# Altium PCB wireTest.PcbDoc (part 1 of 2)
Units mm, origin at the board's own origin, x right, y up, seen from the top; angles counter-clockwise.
Board outline 121.22 x 130.26 mm, 2 copper layers (Top Layer, Bottom Layer); 157 components, 144 nets, 513 pads, 186 vias.
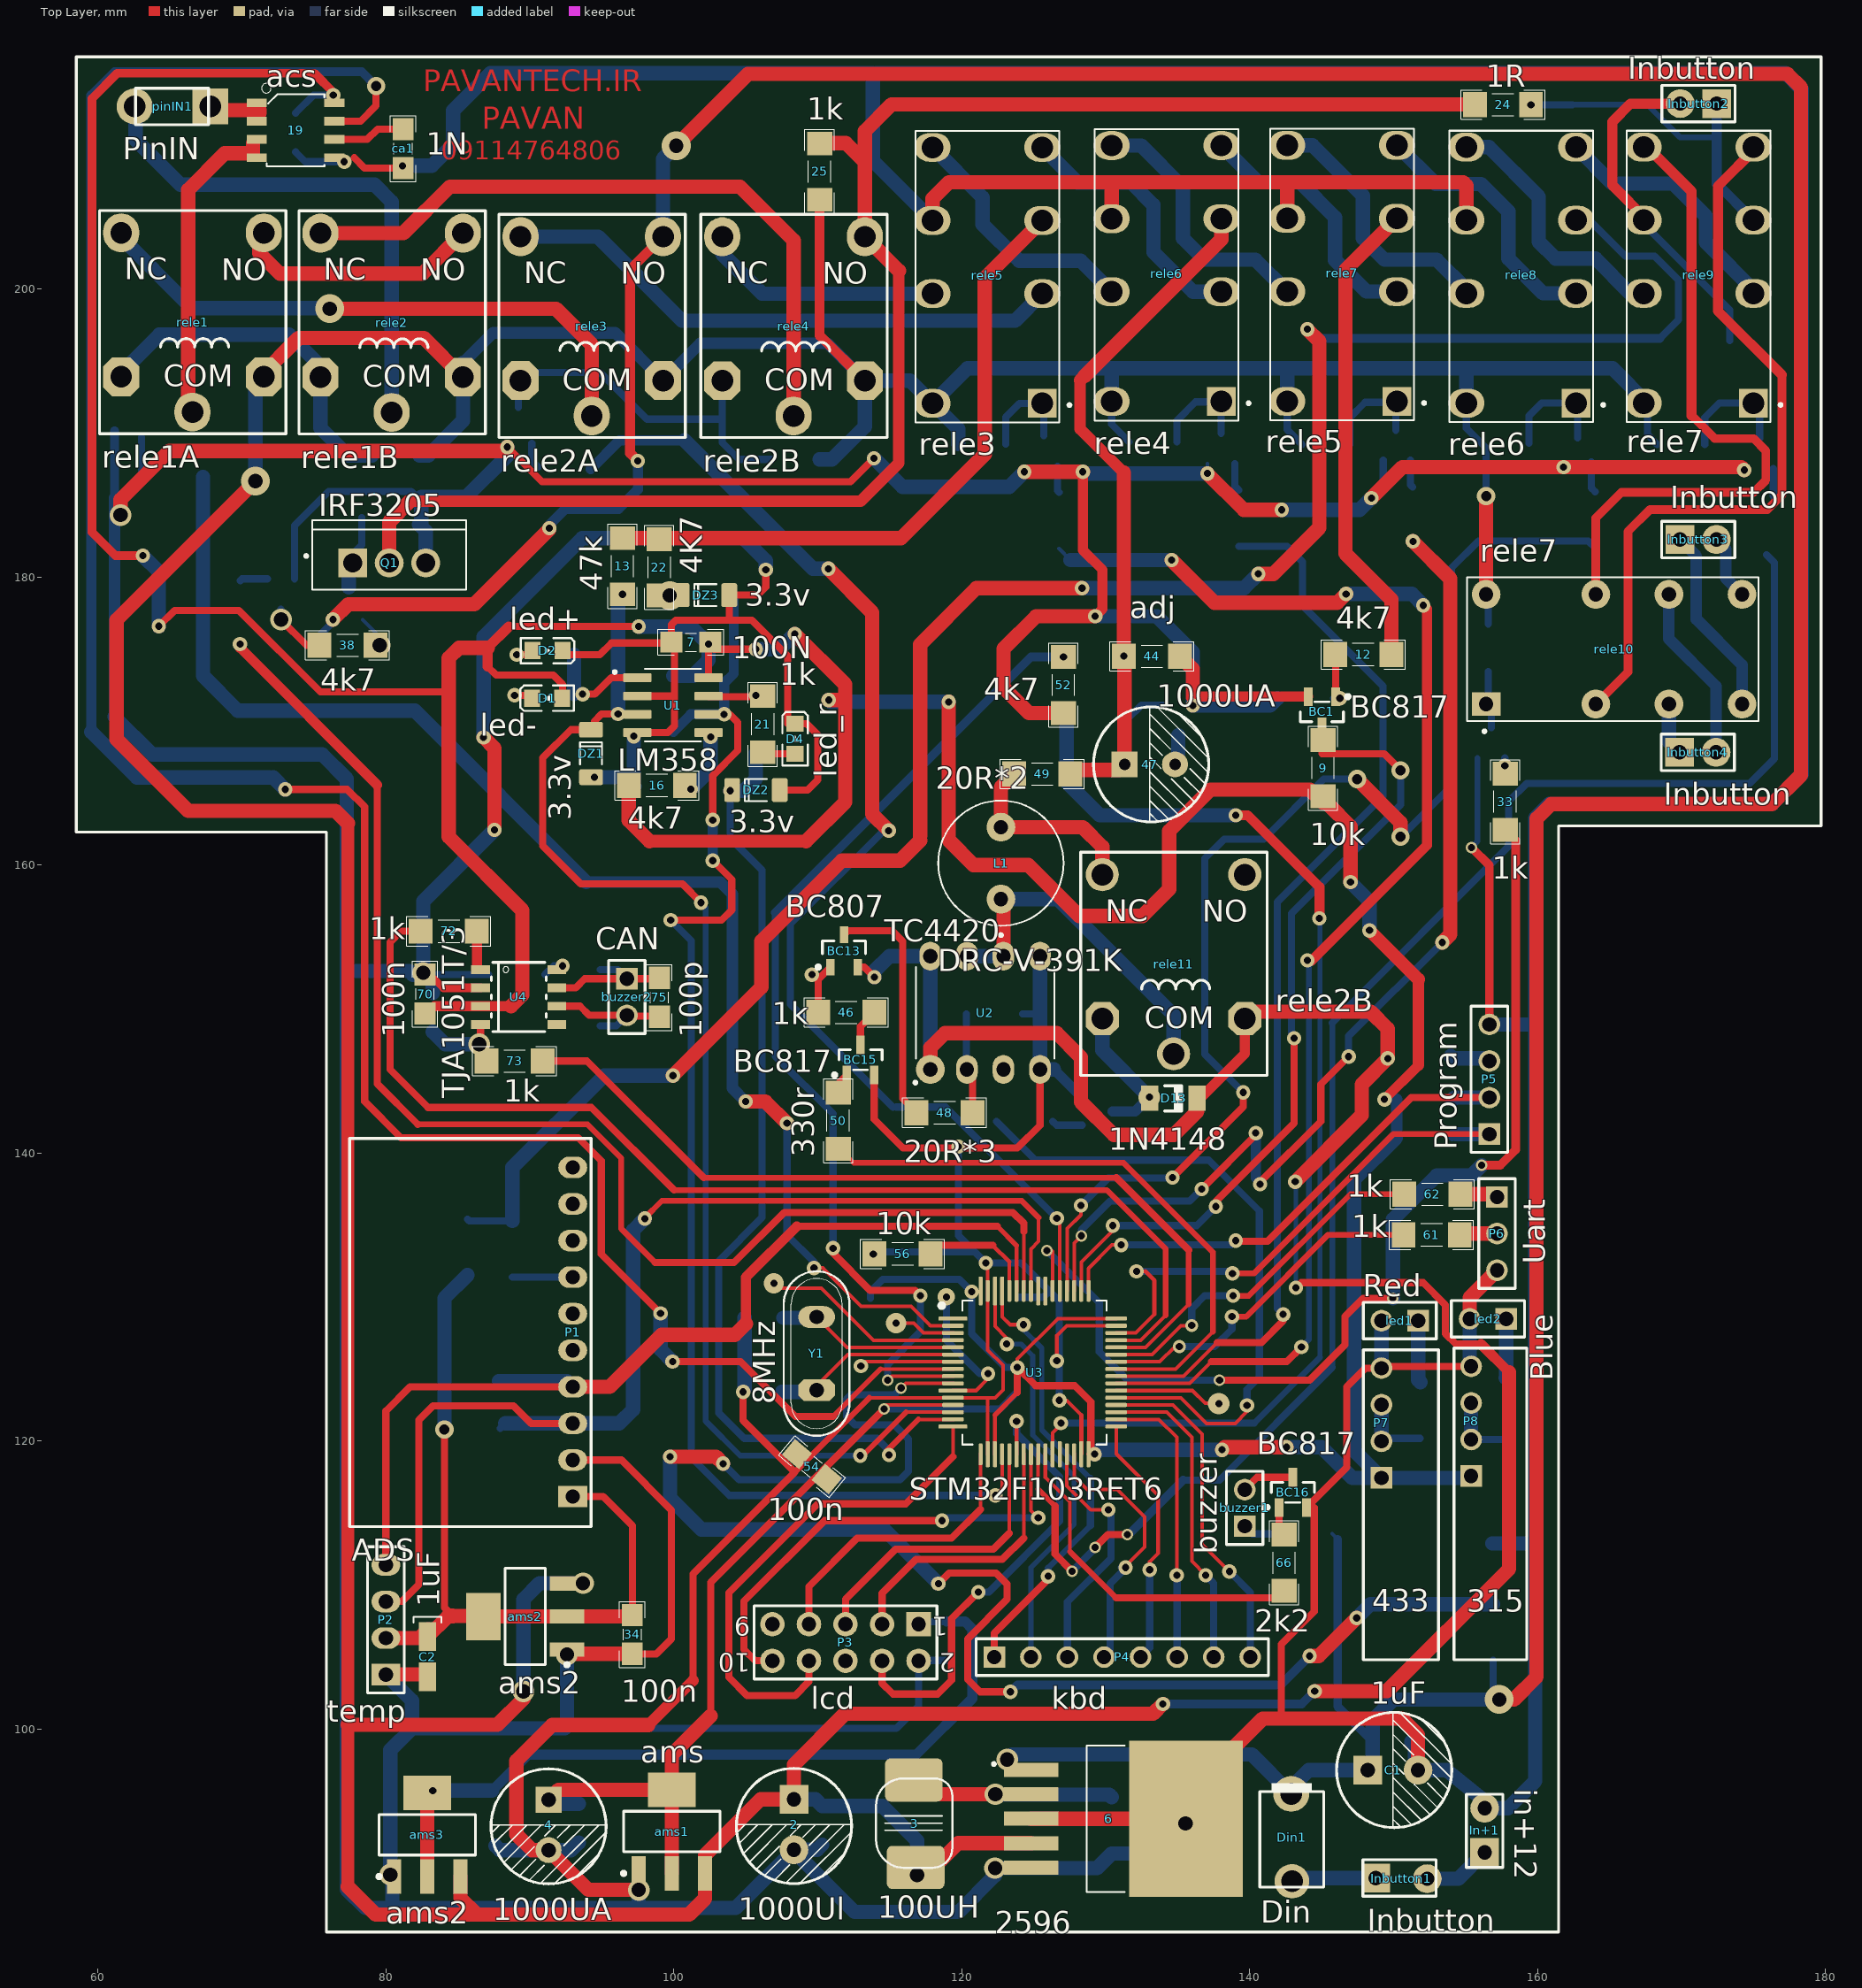
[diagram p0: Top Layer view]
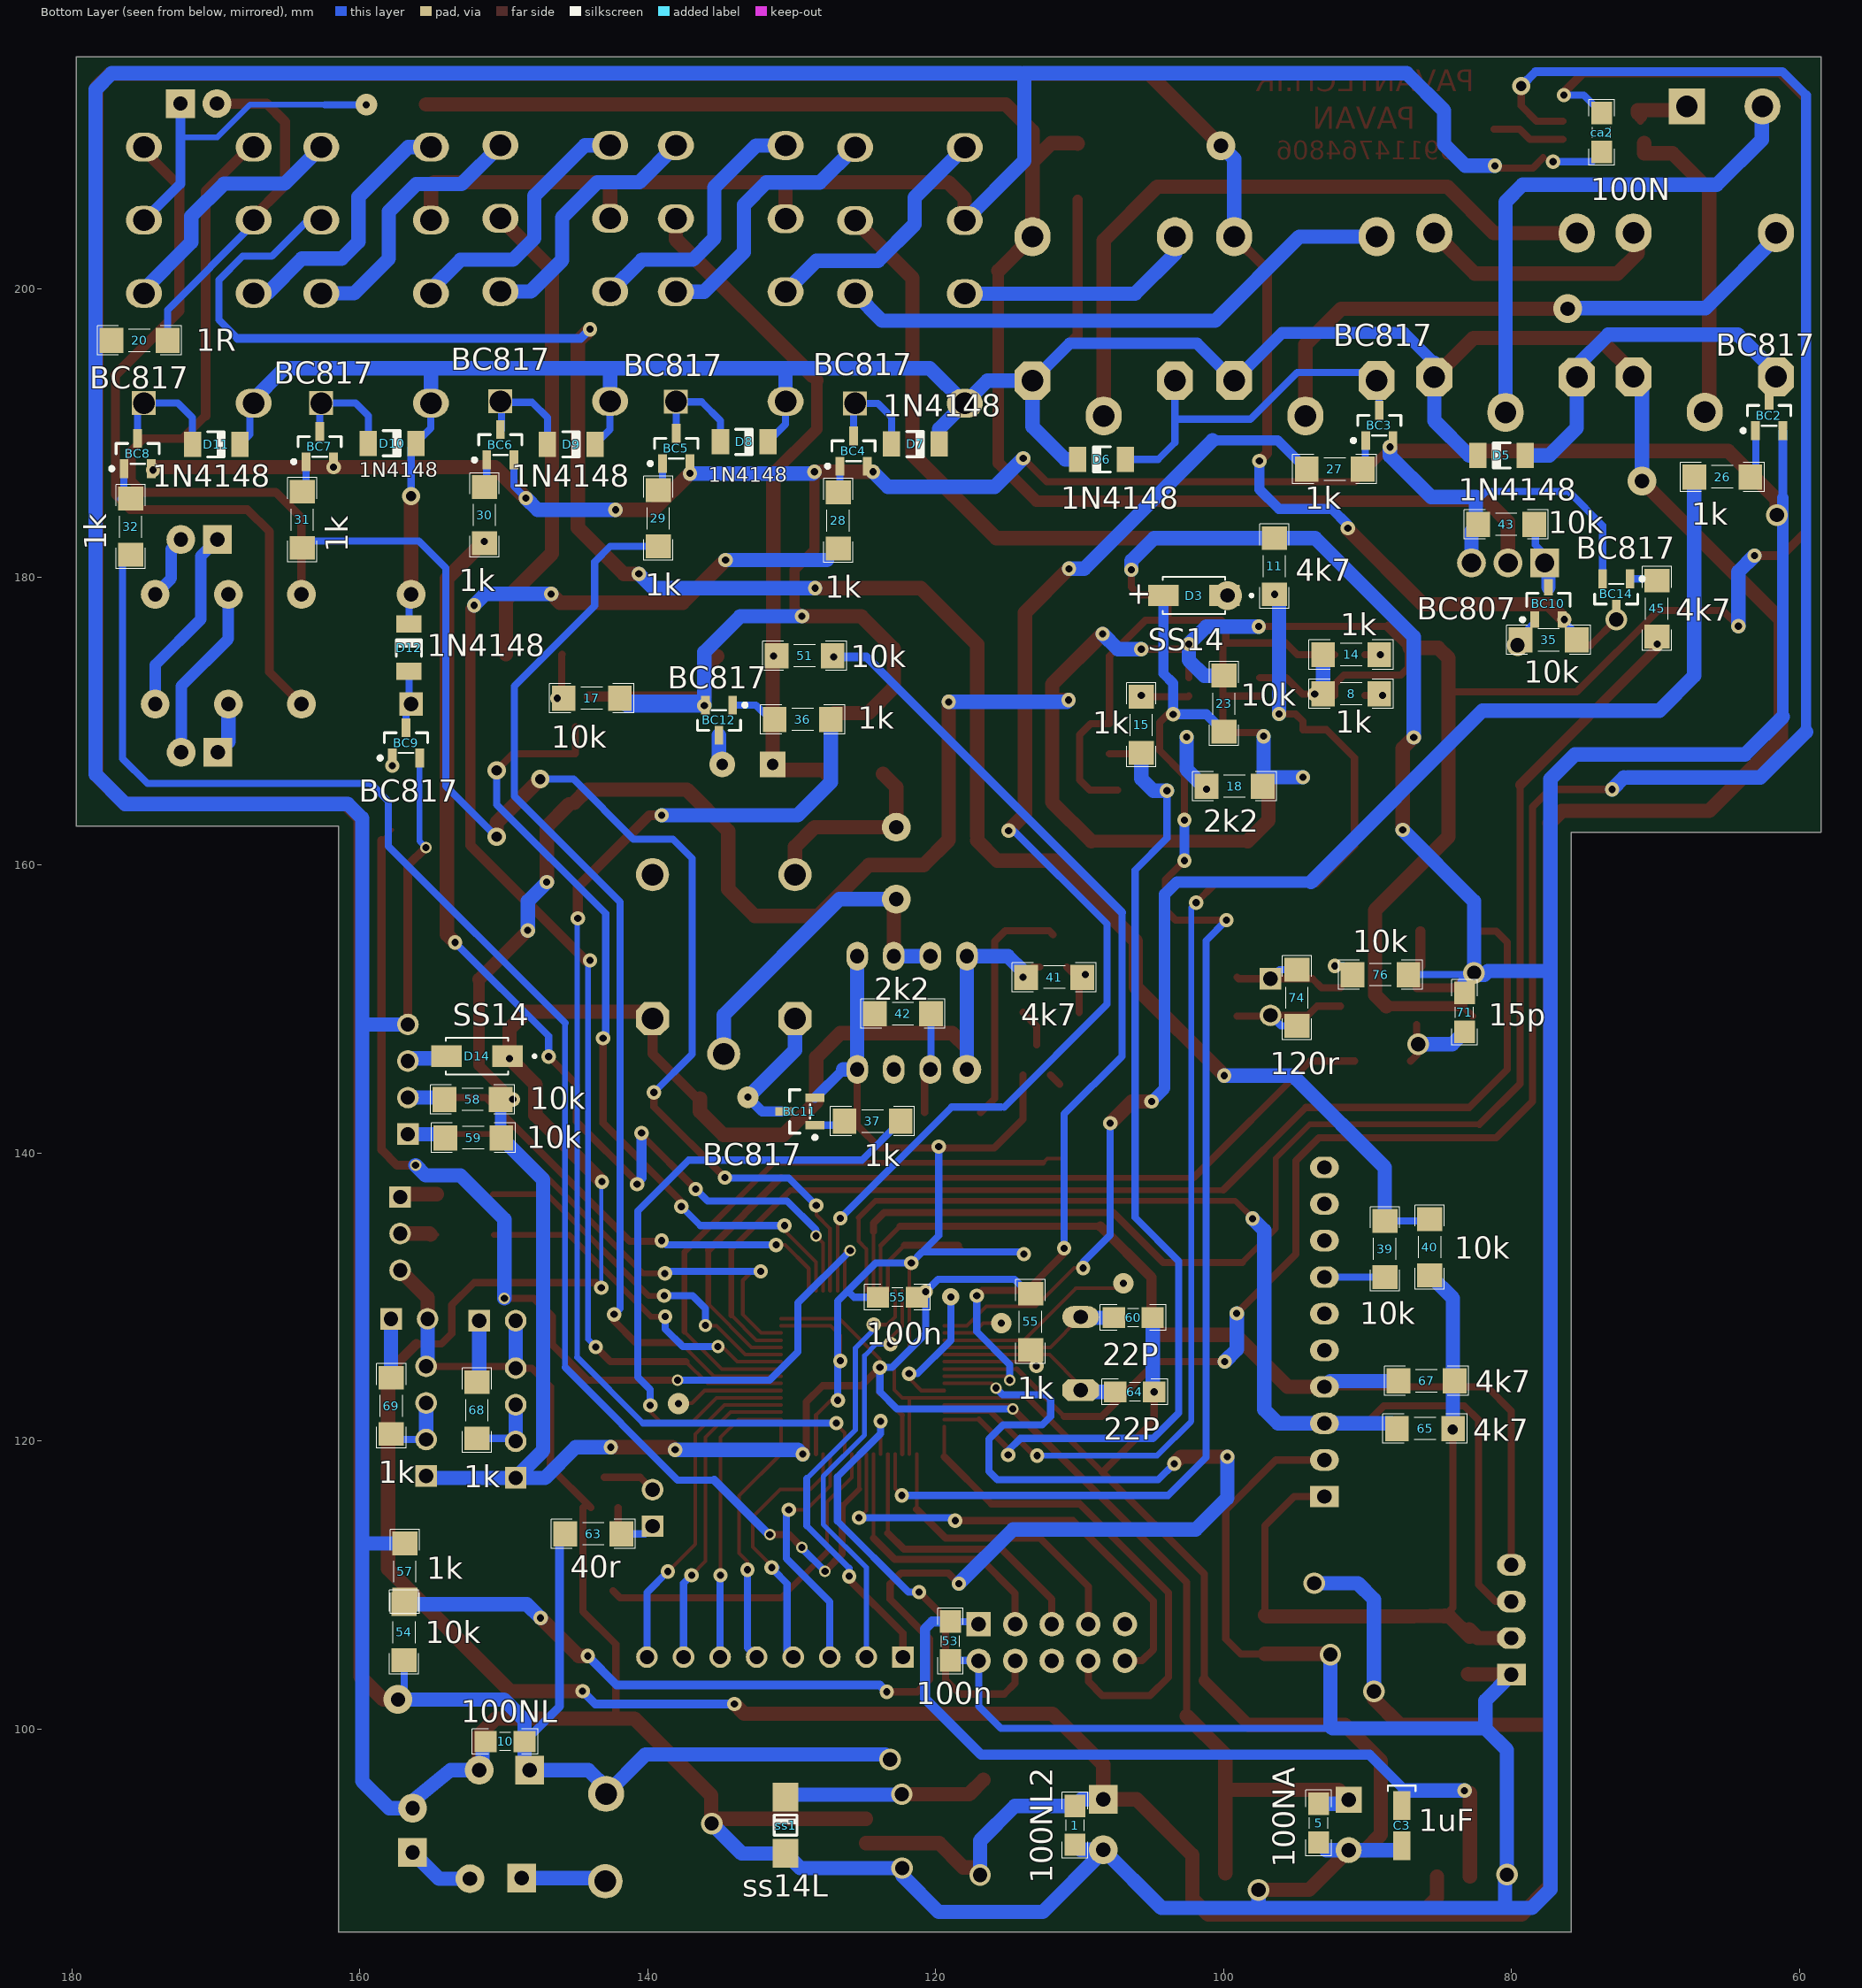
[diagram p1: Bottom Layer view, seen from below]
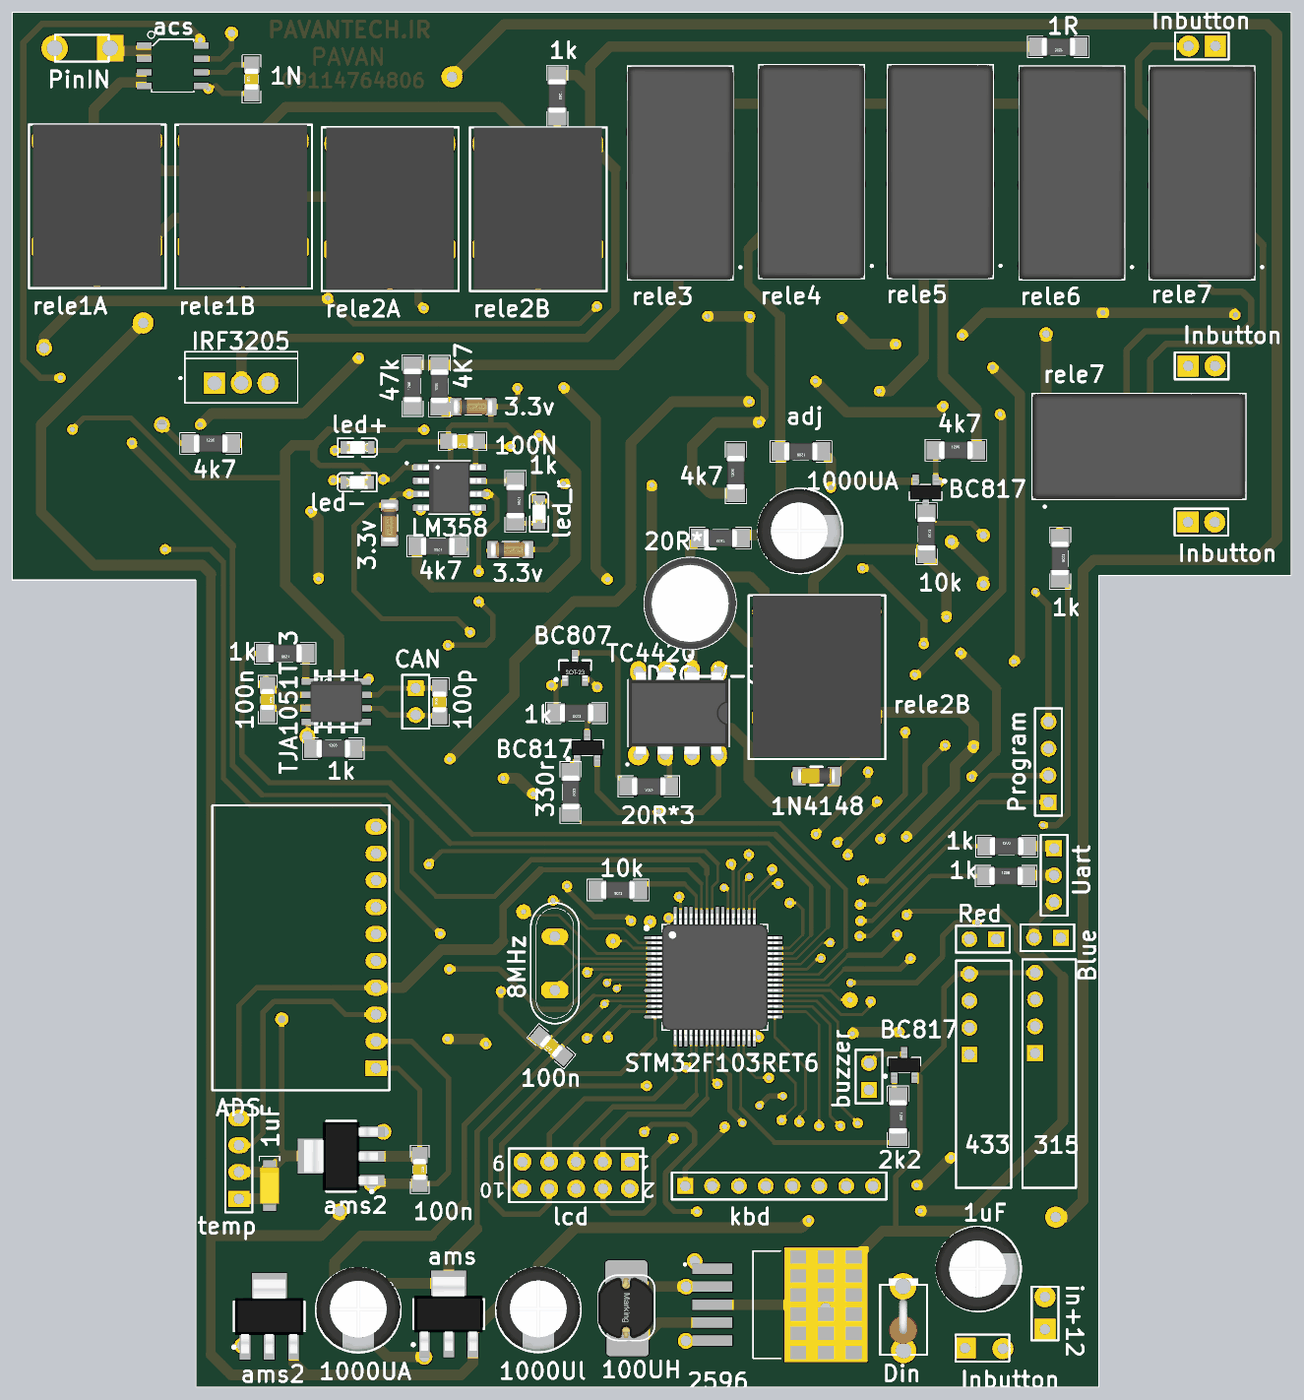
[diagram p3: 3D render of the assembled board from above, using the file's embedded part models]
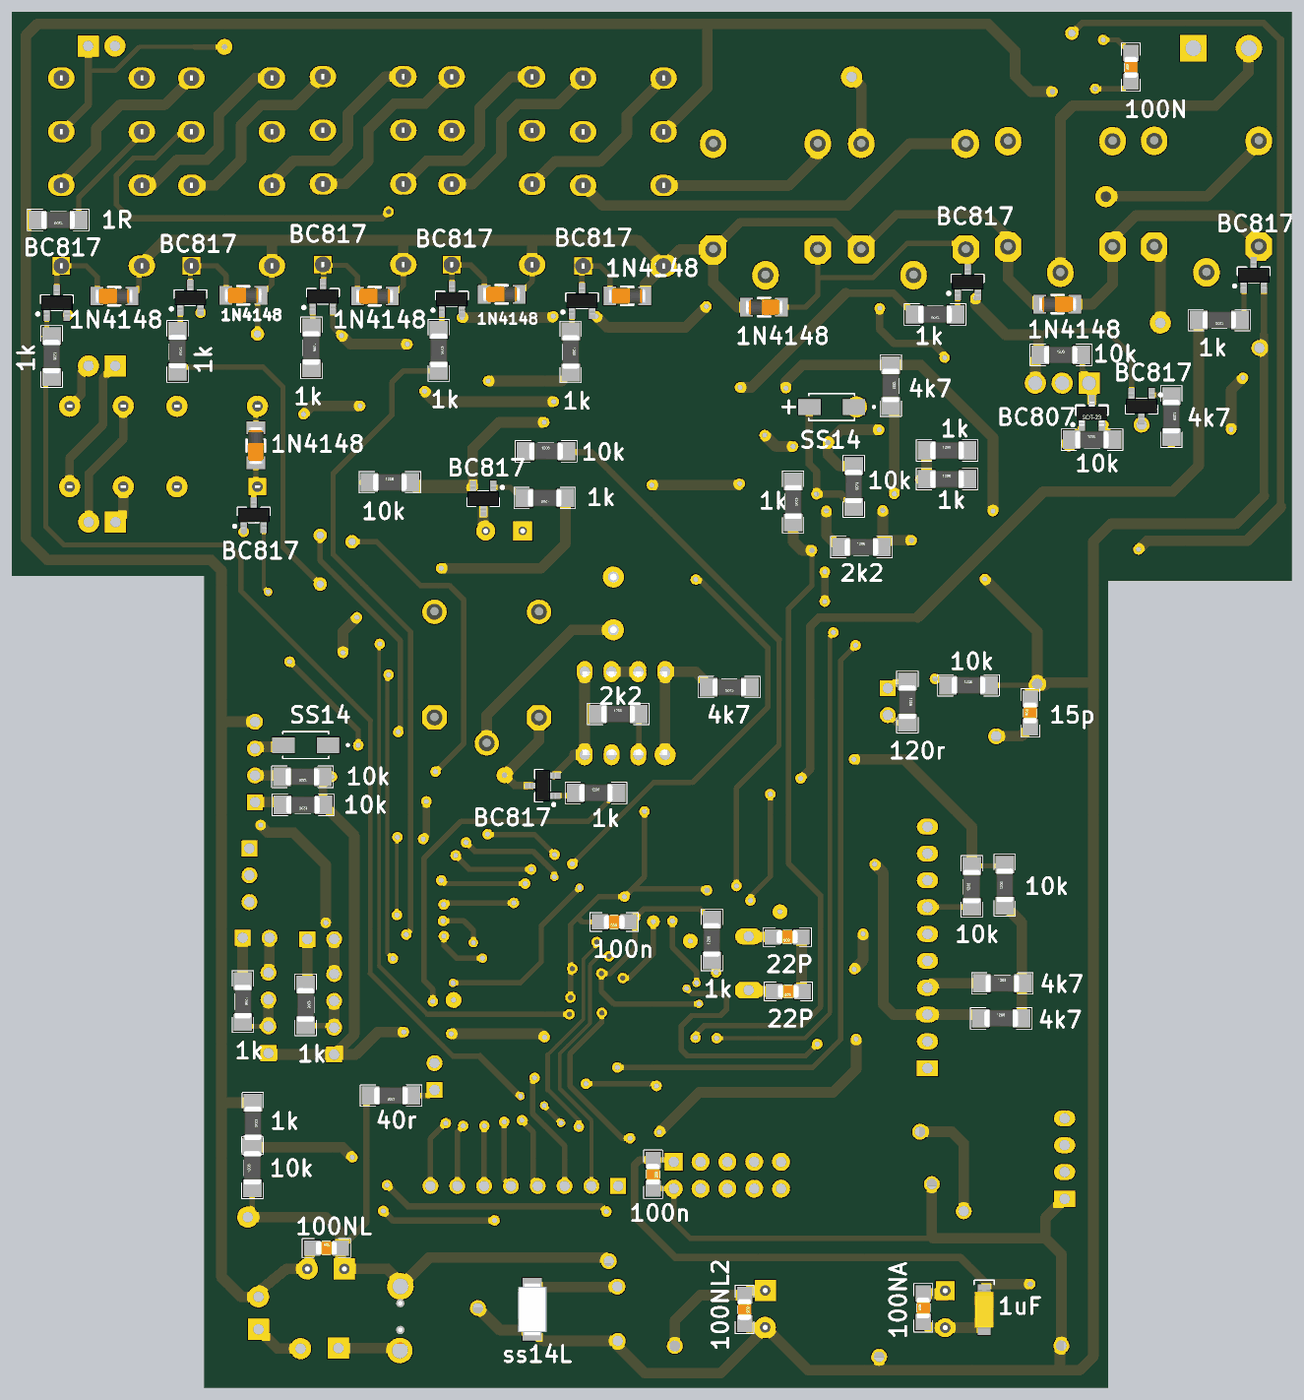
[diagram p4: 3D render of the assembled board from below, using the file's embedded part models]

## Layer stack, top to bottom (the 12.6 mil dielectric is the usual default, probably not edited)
Top Solder: solder mask 0.0102, Solder Resist, Dk 3.5
Top Layer: signal copper 0.0356
Dielectric 1: dielectric 0.32, FR-4, Dk 4.8
Bottom Layer: signal copper 0.0356
Bottom Solder: solder mask 0.0102, Solder Resist, Dk 3.5

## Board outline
58.496,162.274 cw(c58.496,162.281) 58.489,162.281 58.489,216.129 cw(c58.496,216.129) 58.496,216.135 179.705,216.135 cw(c179.705,216.129) 179.712,216.129 179.712,162.712 cw(c179.705,162.712) 179.705,162.706 161.475,162.706 161.475,85.877 cw(c161.468,85.877) 161.468,85.871 75.87,85.871 cw(c75.87,85.877) 75.863,85.877 75.863,162.274

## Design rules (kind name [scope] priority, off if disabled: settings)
Clearance [All] p1: gap=0.1 ignorepadtopadclearanceinfootprint=FALSE
PolygonConnect [All] p1: connectstyle=Relief reliefconductorwidth=0.254 reliefentries=4 polygonreliefangle="90 Angle" airgapwidth=0.254
RoutingVias [All] p1: holewidth=0.5 width=1 viastyle="Through Hole" minholewidth=0.5 minwidth=1 maxholewidth=1 maxwidth=1.5 viatemplateguid#1={EFB9FA06-F7A7-452A-BE94-403044DDEC13} viatemplatename#1=v127h71
SolderMaskExpansion [All] p1: expansion=0.102
Width [All] p1: maxlimit=1 minlimit=0.25 preferedwidth=0.5
30 further rules are at their usual default settings.

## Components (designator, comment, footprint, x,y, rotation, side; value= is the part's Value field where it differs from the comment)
1 "100NL2" CAPC3413X12N 110.312,93.294 r270 bottom
2 "1000Ul" "Cap electrolitic radial 8x12-3.5"#1 108.356,93.345 r270 top value=1uF
3 "100UH" "Inductor SMD 3x3.2mm" 116.662,93.447 r270 top value=4µ7
4 "1000UA" "Cap electrolitic radial 8x12-3.5"#2 91.313,93.32 r270 top value=1uF
5 "100NA" CAPC3413X12N 93.396,93.447 r90 bottom
6 "2596" TO170P1524X483-6N 131.242,93.751 r0 top
7 "100N" CAPC3413X12N 101.194,175.463 r180 top
8 "1k" RESC4817X04N 91.135,171.882 r180 bottom
9 "10k" RESC4817X04N 145.11,166.726 r270 top
10 "100NL" CAPC3413X12N 149.911,99.111 r180 bottom
11 "4k7" RESC4817X04N 96.469,180.746 r270 bottom
12 "4k7" RESC4817X04N 147.904,174.625 r0 top
13 "47k" RESC4817X04N 96.444,180.746 r90 top
14 "1k" RESC4817X04N 91.135,174.6 r180 bottom
15 "1k" RESC4817X04N 105.715,169.723 r270 bottom
16 "4k7" RESC4817X04N 98.831,165.532 r180 top
17 "10k" RESC4817X04N 143.891,171.577 r180 bottom
18 "2k2" RESC4817X04N 99.238,165.456 r180 bottom
19 "acs" SOIC8-1.27-5X4MM 73.736,211.023 r270 top
20 "1R" RESC4817X04N 175.311,196.418 r0 bottom
21 "1k" RESC4817X04N 106.197,169.774 r270 top
22 "4K7" RESC4817X04N 99.009,180.67 r90 top
23 "10k" RESC4817X04N 99.974,171.196 r270 bottom
24 "1R" RESC4817X04N 157.607,212.801 r180 top
25 "1k" RESC4817X04N 110.134,208.153 r270 top
26 "1k" RESC4817X04N 65.354,186.944 r0 bottom
27 "1k" RESC4817X04N 92.278,187.477 r0 bottom
28 "1k" RESC4817X04N 126.771,183.921 r270 bottom
29 "1k" RESC4817X04N 139.268,184.074 r270 bottom
30 "1k" RESC4817X04N 151.333,184.302 r270 bottom
31 "1k" RESC4817X04N 164.008,183.972 r270 bottom
32 "1k" RESC4817X04N 175.92,183.49 r270 bottom
33 "1k" RESC4817X04N 157.759,164.389 r270 top
34 "100n" CAPC3413X12N 97.13,106.553 r270 top
35 "10k" RESC4817X04N 77.419,175.616 r180 bottom
36 "1k" RESC4817X04N 129.235,170.104 r0 bottom
37 "1k" RESC4817X04N 124.384,142.189 r180 bottom
38 "4k7" RESC4817X04N 77.343,175.26 r0 top
39 "10k" RESC4817X04N 88.798,133.325 r90 bottom
40 "10k" RESC4817X04N 85.674,133.452 r90 bottom
41 "4k7" RESC4817X04N 111.76,152.197 r0 bottom
42 "2k2" RESC4817X04N 122.276,149.657 r180 bottom
43 "10k" RESC4817X04N 80.366,183.642 r180 bottom
44 "adj" RESC4817X04N 133.223,174.498 r180 top
45 "4k7" RESC4817X04N 69.901,177.8 r270 bottom
46 "1k" RESC4817X04N 111.989,149.758 r180 top
47 "1000UA" "Cap electrolitic radial 8x12-3.5"#3 133.073,166.98 r0 top value=1uF
48 "20R*3" RESC4817X04N 118.821,142.799 r180 top
49 "20R*2" RESC4817X04N 125.603,166.319 r180 top
50 "330r" RESC4817X04N 111.43,142.24 r270 top
51 "10k" RESC4817X04N 129.108,174.523 r180 bottom
52 "4k7" RESC4817X04N 127.076,172.497 r90 top
53 "100n" CAPC3413X12N 118.974,106.096 r270 bottom
54 "100n" CAPC3413X12N 109.601,118.212 r140 top
54 "10k" RESC4817X04N 156.921,106.705 r90 bottom
55 "100n" CAPC3413X12N 122.657,129.972 r0 bottom
55 "1k" RESC4817X04N 113.411,128.27 r90 bottom
56 "10k" RESC4817X04N 115.9,132.994 r180 top
57 "1k" RESC4817X04N 156.87,110.922 r270 bottom
58 "10k" RESC4817X04N 152.171,143.713 r0 bottom
59 "10k" RESC4817X04N 152.121,141.046 r0 bottom
60 "22P" CAPC3413X12N 106.274,128.549 r0 bottom
61 "1k" RESC4817X04N 152.654,134.315 r0 top
62 "1k" RESC4817X04N 152.705,137.135 r0 top
63 "40r" RESC4817X04N 143.784,113.538 r0 bottom
64 "22P" CAPC3413X12N 106.172,123.393 r0 bottom
65 "4k7" RESC4817X04N 86.004,120.853 r180 bottom
66 "2k2" RESC4817X04N 142.418,111.531 r270 top
67 "4k7" RESC4817X04N 85.903,124.155 r180 bottom
68 "1k" RESC4817X04N 151.867,122.123 r270 bottom
69 "1k" RESC4817X04N 157.81,122.428 r270 bottom
70 "100n" CAPC3413X12N 82.728,151.028 r270 top
71 "15p" CAPC3413X12N 83.261,149.758 r90 bottom
72 "1k" RESC4817X04N 84.379,155.397 r180 top
73 "1k" RESC4817X04N 88.951,146.38 r0 top
74 "120r" RESC4817X04N 94.894,150.774 r270 bottom
75 "100p" CAPC3413X12N 99.009,150.8 r90 top
76 "10k" RESC4817X04N 89.103,152.375 r180 bottom
ams1 "ams" MP04A_N 99.873,92.862 r90 top
ams2 "ams2" MP04A_N 89.687,107.798 r180 top
ams3 "ams2" MP04A_N 82.88,92.634 r90 top
BC1 "BC817" SOT23_N 145.034,170.637 r270 top
BC2 "BC817" SOT23_N 62.103,191.211 r90 bottom
BC3 "BC817" SOT23_N 89.179,190.525 r90 bottom
BC4 "BC817" SOT23_N 125.705,188.747 r90 bottom
BC5 "BC817" SOT23_N 138.024,188.925 r90 bottom
BC6 "BC817" SOT23_N 150.241,189.179 r90 bottom
BC7 "BC817" SOT23_N 162.789,189.052 r90 bottom
BC8 "BC817" SOT23_N 175.438,188.57 r90 bottom
BC9 "BC817" SOT23_N 156.794,168.478 r90 bottom
BC10 "BC807" SOT23_BEC_N 77.434,178.163 r90 bottom
BC11 "BC817" SOT23_N 129.438,142.875 r0 bottom
BC12 "BC817" SOT23_N 135.052,170.053 r270 bottom
BC13 "BC807" SOT23_BEC_N 111.836,154.026 r90 top
BC14 "BC817" SOT23_N 72.72,178.816 r270 bottom
BC15 "BC817" SOT23_N 112.979,146.456 r90 top
BC16 "BC817" SOT23_N 143.012,116.417 r90 top
buzzer1 "buzzer" HDR1X2#1 139.67,114.071 r90 top
buzzer2 "CAN" HDR1X2#1 96.749,152.095 r270 top
C1 "1uF" "Cap electrolitic radial 8x12-3.5"#1 149.959,97.13 r0 top
C2 "1uF" "Cap1206_(3216X18L)Size A" 82.906,106.401 r270 top
C3 "1uF" "Cap1206_(3216X18L)Size A" 87.63,94.671 r270 bottom
ca1 "1N" CAPC3413X12N 81.204,209.753 r90 top
ca2 "100N" CAPC3413X12N 73.736,210.871 r90 bottom
D1 "led-" LED_SMD_0805 91.211,171.577 r0 top
D2 "led+" LED_SMD_0805 91.237,174.879 r180 top
D3 "SS14" DIOM4325X250N 102.057,178.714 r0 bottom
D4 "led_r" LED_SMD_0805 108.433,168.758 r270 top
D5 "1N4148" "Diode 1n4148 SMD" 79.045,188.443 r0 bottom
D6 "1N4148" "Diode 1n4148 SMD" 106.832,188.163 r0 bottom
D7 "1N4148" "Diode 1n4148 SMD" 123.061,189.23 r180 bottom
D8 "1N4148" "Diode 1n4148 SMD" 134.95,189.382 r180 bottom
D9 "1N4148" "Diode 1n4148 SMD" 146.964,189.205 r180 bottom
D10 "1N4148" "Diode 1n4148 SMD" 159.41,189.281 r180 bottom
D11 "1N4148" "Diode 1n4148 SMD" 171.628,189.205 r180 bottom
D12 "1N4148" "Diode 1n4148 SMD" 156.591,173.433 r90 bottom
D13 "1N4148" "Diode 1n4148 SMD" 133.071,143.789 r0 top
D14 "SS14" DIOM4325X250N 151.867,146.71 r0 bottom
Din1 "Din" "Diode 1W Stand" 142.926,92.634 r90 top
DZ1 "3.3v" "SOD80, LL-34" 94.259,167.742 r270 top value=12V
DZ2 "3.3v" "SOD80, LL-34" 105.715,165.202 r0 top value=12V
DZ3 "3.3v" "SOD80, LL-34" 102.21,178.74 r0 top value=12V
In+1 "in+12" HDR1X2#2 156.337,91.643 r90 top
Inbutton1 "Inbutton" HDR1X2#3 149.149,89.637 r0 top
Inbutton2 "Inbutton" HDR1X2#4 172.466,212.877 r180 top
Inbutton3 "Inbutton" HDR1X2#4 169.901,182.601 r0 top
Inbutton4 "Inbutton" HDR1X2#4 169.875,167.818 r0 top
L1 "DRC-V-391K" IND_DRC-V-391K 122.733,160.122 r90 top
led1 "Red" HDR1X2#1 151.714,128.346 r180 top
led2 "Blue" HDR1X2#1 157.836,128.473 r180 top
P1 "ADS" HDR1X10 92.989,116.129 r90 top
P2 "temp" HDR1X4#1 80.01,103.759 r90 top
P3 "lcd" HDR2X5 117.018,107.264 r180 top
P4 "kbd" HDR1X8 122.276,104.978 r0 top
P5 "Program" HDR1X4#2 156.667,141.3 r90 top
P6 "Uart" HDR1X3 157.201,136.931 r270 top
P7 "433" HDR1X4#2 149.174,117.424 r90 top
P8 "315" HDR1X4#2 155.397,117.551 r90 top
pinIN1 "PinIN" HDR1X2#5 66.421,212.674 r180 top
Q1 "IRF3205" TO254P1067X483X3124-3P 77.699,180.975 r0 top
rele1 "rele1A" "Relay 15.40x12.10x13.10"#1 66.57,191.454 r0 top
rele2 "rele1B" "Relay 15.40x12.10x13.10"#1 80.413,191.428 r0 top
rele3 "rele2A" "Relay 15.40x12.10x13.10"#1 94.31,191.186 r0 top
rele4 "rele2B" "Relay 15.40x12.10x13.10"#1 108.328,191.182 r0 top
rele5 "rele3" RELAY_9-1393792-3#1 121.793,200.838 r90 top
rele6 "rele4" RELAY_9-1393792-3#1 134.239,200.965 r90 top
rele7 "rele5" RELAY_9-1393792-3#1 146.431,200.982 r90 top
rele8 "rele6" RELAY_9-1393792-3#1 158.877,200.855 r90 top
rele9 "rele7" RELAY_9-1393792-3#1 171.196,200.855 r90 top
rele10 "rele7" RELAY_9-1393792-3#2 165.219,174.981 r0 top
rele11 "rele2B" "Relay 15.40x12.10x13.10"#2 134.725,146.877 r0 top
ss1 "ss14L" "Diode 1N4007 SMD" 130.429,91.338 r90 bottom
U1 "LM358" SOIC127P599X175-8N 99.949,171.094 r0 top
U2 "TC4420" DIP787W46P254L927H533Q8 121.641,149.733 r90 top
U3 "STM32F103RET6" QFP50P1200X1200X160-64N 125.07,124.739 r0 top
U4 "TJA1051T/3" SOT96-1 89.23,150.825 r270 top
Y1 "8MHz" My_Crystal 109.931,126.06 r90 top

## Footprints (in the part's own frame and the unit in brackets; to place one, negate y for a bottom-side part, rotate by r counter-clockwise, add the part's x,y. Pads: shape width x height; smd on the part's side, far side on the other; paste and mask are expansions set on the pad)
"Cap1206_(3216X18L)Size A" [mm] "Chip Capacitor, 2-Leads, Body 3.2x1.6mm, IPC High Density, chip Tantalum"
  rect 1.999x1.199 smd: 1(0,0) 2(2.8,0)
  silkscreen extent -1.38,-0.97 -0.99,0.97, body extent -0.43,-0.9 3.21,0.9, height 1.8
"Cap electrolitic radial 8x12-3.5"#1 [mm] "Cap electrolitic radial 8x12-3.5-Design:Abbas Basereh"
  rect 2x2 hole 1: 1(-1.75,0)
  round 2 hole 1: 2(1.75,0)
  silkscreen extent -3.9,-4 4.1,4, body extent -4,-4 4,4, height 12.3
"Cap electrolitic radial 8x12-3.5"#2 [mm] "Cap electrolitic radial 8x12-3.5-Design:Abbas Basereh"
  rect 1.8x1.8 hole 1: 1(-1.75,0)
  round 1.8 hole 1: 2(1.75,0)
  silkscreen extent -3.9,-4 4.1,4, body extent -4,-4 4,4, height 12.3
"Cap electrolitic radial 8x12-3.5"#3 [mm] "Cap electrolitic radial 8x12-3.5-Design:Abbas Basereh"
  rect 1.8x1.8 hole 0.8: 1(-1.75,0)
  round 1.8 hole 0.8: 2(1.75,0)
  silkscreen extent -3.9,-4 4.1,4, body extent -4,-4 4,4, height 12.3
CAPC3413X12N [mm] "Chip Capacitor, 2-Leads, Body 3/40x1/30mm, IPC Medium Density-Design:Abbas Basereh"
  rect 1.55x1.45 smd: 1(-1.35,0) 2(1.35,0)
  silkscreen extent -2.29,-0.89 2.29,0.89, body extent -1,-0.63 1,0.62, height 0.78
"Diode 1N4007 SMD" [mm] "DO-214AC 1N4001-4007"
  rect 2x1.8 smd: 1(0,0) 2(3.92,0)
  silkscreen extent 1.27,-0.81 2.67,0.83, body extent -0.54,-1.36 4.46,1.34, height 2.16
"Diode 1n4148 SMD" [mm] "Mini MELF SOD-80"
  rect 1.2x1.75 smd: 1(0,0) 2(3.3,0)
  silkscreen extent 1.04,-0.87 2.22,0.87, body extent -0.13,-0.75 3.37,0.75, height 1.55
"Diode 1W Stand" [mm]
  round 2.4 hole 1.5: 1(-3.226,-0.025)
  round 2.5 hole 1.5: 2(2.845,0.025)
  silkscreen extent -3.63,-2.24 3.58,2.21, body extent -2.62,-1.32 1.65,1.35, height 7.39
DIOM4325X250N [mm]
  rect 2.12x1.5 smd: A(2.115,0) C(-2.115,0)
  silkscreen extent -4.1,-1.28 2.16,1.28
DIP787W46P254L927H533Q8 [mm]
  round 2 hole 1: 1(-3.935,3.81)
  oval 2x1.5 hole 1: 2(-3.935,1.27) 3(-3.935,-1.27) 4(-3.935,-3.81) 5(3.935,-3.81) 6(3.935,-1.27) 7(3.935,1.27) 8(3.935,3.81)
  silkscreen extent -4.95,-4.8 3.18,4.95, body extent -3.96,-4.75 3.96,4.75, height 5.08
HDR1X2#1 [mm] "Connector; Header; 2 Position"
  rect 1.5x1.5 hole 1: 1(0,0)
  round 1.5 hole 1: 2(2.54,0)
  silkscreen extent -1.27,-1.27 3.81,1.27
HDR1X2#2 [mm] "Connector; Header; 2 Position"
  rect 2x2 hole 1: 1(-0.229,0)
  round 2 hole 1: 2(2.845,0)
  silkscreen extent -1.27,-1.27 3.81,1.27
HDR1X2#3 [mm] "Connector; Header; 2 Position"
  rect 2x2 hole 1: 1(-0.381,0)
  round 2 hole 1: 2(3.2,-0.051)
  silkscreen extent -1.27,-1.27 3.81,1.27
HDR1X2#4 [mm] "Connector; Header; 2 Position"
  rect 2x2 hole 1: 1(0,0)
  round 2 hole 1: 2(2.54,0)
  silkscreen extent -1.27,-1.27 3.81,1.27
HDR1X2#5 [mm] "Connector; Header; 2 Position"
  rect 2.5x2.5 hole 1.5: 1(-1.397,0)
  round 2.5 hole 1.5: 2(3.861,0)
  silkscreen extent -1.27,-1.27 3.81,1.27
HDR1X3 [mm] "Connector; Header; 3 Position"
  rect 1.5x1.5 hole 1: 1(0,0)
  round 1.5 hole 1: 2(2.54,0) 3(5.08,0)
  silkscreen extent -1.27,-1.27 6.35,1.27
HDR1X4#1 [mm] "Connector; Header; 4 Position"
  rect 1.5x2 hole 1: 1(0,0)
  oval 1.5x2 hole 1: 2(2.54,0) 3(5.08,0) 4(7.62,0)
  silkscreen extent -1.27,-1.27 8.89,1.27
HDR1X4#2 [mm] "Connector; Header; 4 Position"
  rect 1.5x1.5 hole 1: 1(0,0)
  round 1.5 hole 1: 2(2.54,0) 3(5.08,0) 4(7.62,0)
  silkscreen extent -1.27,-1.27 8.89,1.27
HDR1X8 [mm] "Connector; Header; 8 Position"
  rect 1.5x1.5 hole 1: 1(0,0)
  round 1.5 hole 1: 2(2.54,0) 3(5.08,0) 4(7.62,0) 5(10.16,0) 6(12.7,0) 7(15.24,0) 8(17.78,0)
  silkscreen extent -1.27,-1.27 19.05,1.27
HDR1X10 [mm] "Connector; Header; 10 Position"
  rect 1.5x2 hole 1: 1(0,0)
  oval 1.5x2 hole 1: 2(2.54,0) 3(5.08,0) 4(7.62,0) 5(10.16,0) 6(12.7,0) 7(15.24,0) 8(17.78,0) 9(20.32,0) 10(22.86,0)
  silkscreen extent -2.08,-1.27 24.87,15.49
HDR2X5 [mm] "Connector; Header; 5x2 Position"
  rect 1.7x1.7 hole 1: 1(0,0)
  round 1.7 hole 1: 2(0,2.54) 3(2.54,0) 4(2.54,2.54) 5(5.08,0) 6(5.08,2.54) 7(7.62,0) 8(7.62,2.54) 9(10.16,0) 10(10.16,2.54)
  silkscreen extent -1.27,-1.27 11.43,3.81
IND_DRC-V-391K [mm]
  round 2 hole 1: 1(-2.5,0) 2(2.5,0)
  silkscreen extent -5.1,-4.35 4.35,4.35, body extent -4.35,-4.35 4.35,4.35, height 12.5
"Inductor SMD 3x3.2mm" [mil] "Inductor 4.7µH SMD 3x3.2mm"
  round 20 on Mech15: 0(0,0)
  rrect25% 118.11x157.48 smd: 1(-118,1) 2(121,6)
  silkscreen extent -122,-102 122,106, body extent -114,-102 114,102, height 177
LED_SMD_0805 [mm] "SMD Mono-color Chip LED, body 2.0x1.25mm"
  rect 1.1x1.2 smd: 1(-1.05,0) 2(1.05,0)
  silkscreen extent -1.85,-0.88 1.85,0.88, body extent -1,-0.62 1,0.63, height 0.7
MP04A_N [mm] "SOT223, 4-Leads, Body 6.5x3.5mm, Pitch 2.3mm, Lead Span 7mm, IPC Medium Density"
  rect 2.4x1 smd: 1(-2.9,2.3) 2(-2.9,0) 3(-2.9,-2.3)
  rect 2.4x3.3 smd: 4(2.9,0)
  silkscreen extent -3.02,-3.35 1.4,3.47, body extent -3.49,-3.24 3.49,3.24, height 1.64
My_Crystal [mm]
  oct 1.524x2.54 hole 1: 1(-2.54,0)
  oval 1.524x2.54 hole 1: 2(2.54,0)
  silkscreen extent -5.71,-2.29 5.71,2.29
QFP50P1200X1200X160-64N [mm]
  rrect50% 2x0.28 smd: 1(-5.67,3.75) 11(-5.67,-1.25) 16(-5.67,-3.75)
  rrect50% 1.49x0.28 smd: 2(-5.67,3.25) 3(-5.67,2.75) 4(-5.67,2.25) 5(-5.67,1.75) 6(-5.67,1.25) 7(-5.67,0.75) 8(-5.67,0.25) 9(-5.67,-0.25) 10(-5.67,-0.75) 12(-5.67,-1.75) 13(-5.67,-2.25) 14(-5.67,-2.75) 15(-5.67,-3.25) 33(5.67,-3.75) 34(5.67,-3.25) 35(5.67,-2.75) 36(5.67,-2.25) 37(5.67,-1.75) 38(5.67,-1.25) 39(5.67,-0.75) 40(5.67,-0.25) 41(5.67,0.25) 42(5.67,0.75) 43(5.67,1.25) 44(5.67,1.75) 45(5.67,2.25) 46(5.67,2.75) 47(5.67,3.25) 48(5.67,3.75)
  rrect50% 0.28x1.49 smd: 17(-3.75,-5.67) 20(-2.25,-5.67) 21(-1.75,-5.67) 23(-0.75,-5.67) 24(-0.25,-5.67) 25(0.25,-5.67) 26(0.75,-5.67) 29(2.25,-5.67) 30(2.75,-5.67) 49(3.75,5.67) 50(3.25,5.67) 51(2.75,5.67) 52(2.25,5.67) 53(1.75,5.67) 54(1.25,5.67) 57(-0.25,5.67) 58(-0.75,5.67) 59(-1.25,5.67) 60(-1.75,5.67) 63(-3.25,5.67)
  rrect50% 0.28x1.8 smd: 18(-3.25,-5.67) 19(-2.75,-5.67) 22(-1.25,-5.67) 27(1.25,-5.67) 28(1.75,-5.67) 31(3.25,-5.67) 32(3.75,-5.67)
  rrect50% 0.28x2 smd: 55(0.75,5.67) 56(0.25,5.67) 61(-2.25,5.67) 62(-2.75,5.67) 64(-3.75,5.67)
  silkscreen extent -6.6,-5 5,5, body extent -6,-6 6,6, height 1.6
"Relay 15.40x12.10x13.10"#1 [mm]
  oval 2.5x2.7 hole 1.5: 1(0,0) 2(-4.95,12.45) 3(4.95,12.45)
  oct 2.5x2.7 hole 1.5: 4(-4.95,2.45) 5(4.95,2.45)
  silkscreen extent -6.45,-1.5 6.5,14, body extent -6.05,-1.3 6.05,14, height 16.1
"Relay 15.40x12.10x13.10"#2 [mm]
  round 2.3 hole 1.5: 1(0,0) 2(-4.95,12.45) 3(4.95,12.45)
  oct 2.3x2.3 hole 1.5: 4(-4.95,2.45) 5(4.95,2.45)
  silkscreen extent -6.45,-1.5 6.5,14, body extent -6.05,-1.3 6.05,14, height 16.1
RELAY_9-1393792-3#1 [mm]
  rect 2x2 / inner round 1.65 / far side rect 1.65x1.65 hole 1.5: 1(-8.78,-3.81)
  oval 2x2.5 hole 1.5: 4(-1.16,-3.81) 6(3.92,-3.81) 8(9,-3.81) 9(9,3.81) 11(3.92,3.81) 13(-1.16,3.81) 16(-8.78,3.81)
  silkscreen extent -10.1,-5.8 10.14,5, body extent -10.1,-5 10.1,5, height 10.9
RELAY_9-1393792-3#2 [mm]
  rect 2x1.65 / inner oval 2x1.65 / far side rect 1.65x1.65 hole 1: 1(-8.78,-3.81)
  round 2 hole 1: 4(-1.16,-3.81) 6(3.92,-3.81) 8(9,-3.81) 9(9,3.81) 11(3.92,3.81) 13(-1.16,3.81) 16(-8.78,3.81)
  silkscreen extent -10.1,-5.8 10.14,5, body extent -10.1,-5 10.1,5, height 10.9
RESC4817X04N [mm] "Chip Resistor, 2-Leads, Body 4/80x1/70mm, IPC Medium Density-Design:Abbas Basereh"
  rect 1.65x1.75 smd: 1(-1.95,0) 2(1.95,0)
  silkscreen extent -2.92,-1.02 2.92,1.02, body extent -1.6,-0.8 1.6,0.8, height 1
"SOD80, LL-34" [mm] "Diode, MiniMELF"
  round 0.5 on Mech15: 0(0,0)
  rrect25% 1.1x1.65 smd: 1(1.65,0) 2(-1.65,0)
  silkscreen extent -0.76,-0.76 0.76,0.76, body extent -1.88,-0.8 1.82,0.8, height 1.6
SOIC8-1.27-5X4MM [mm]
  rect 0.6x1.4 smd: 1(-1.905,-2.7) 2(-0.635,-2.7) 3(0.635,-2.7) 4(1.905,-2.7) 5(1.905,2.7) 6(0.635,2.7) 7(-0.635,2.7) 8(-1.905,2.7)
  silkscreen extent -3.25,-2.36 2.5,2
SOIC127P599X175-8N [mm]
  rrect25% 1.97x0.6 smd: 1(-2.47,1.905) 2(-2.47,0.635) 3(-2.47,-0.635) 4(-2.47,-1.905) 5(2.47,-1.905) 6(2.47,-0.635) 7(2.47,0.635) 8(2.47,1.905)
  silkscreen extent -4.14,-2.52 1.95,2.52, body extent -3,-2.45 3,2.45, height 1.75
SOT23_BEC_N [mm] "SOT23, 3-Leads, Body 2.9x1.3mm, Pitch 0.95mm, Lead Span 2.4mm, IPC Medium Density"
  rect 1.15x0.6 smd: 1(-1.125,0.95) 2(-1.125,-0.95) 3(1.125,0)
  silkscreen extent -1.25,-1.5 0.7,1.93, body extent -1.23,-1.45 1.07,1.45, height 1
SOT23_N [mm] "SOT23, 3-Leads, Body 2.9x1.3mm, Pitch 0.95mm, Lead Span 2.3mm, IPC Medium Density"
  rect 1.3x0.6 smd: 1(-1.05,0.95) 2(-1.05,-0.95) 3(1.05,0)
  silkscreen extent -1.17,-1.5 0.7,1.93, body extent -1.27,-1.5 1.27,1.5, height 1.1
SOT96-1 [mm]
  rect 0.6x1.3 smd: 1(-1.905,-2.65) 2(-0.635,-2.65) 3(0.635,-2.65) 4(1.905,-2.65) 5(1.905,2.65) 6(0.635,2.65) 7(-0.635,2.65) 8(-1.905,2.65)
  silkscreen extent -2.4,-1.9 2.4,1.91, body extent -3,-2.45 3,2.45, height 1.75
TO170P1524X483-6N [mm]
  rect 3.79x0.99 smd: 1(-6.4,3.4) 2(-6.4,1.7) 3(-6.4,0) 4(-6.4,-1.7) 5(-6.4,-3.4)
  rect 7.88x10.84 smd paste-6: 6(4.35,0)
  silkscreen extent -9.1,-5.08 0.09,5.08
TO254P1067X483X3124-3P [mm]
  rect 2.01x2.01 hole 1.34: 1(0,0)
  round 2.01 hole 1.34: 2(2.54,0) 3(5.08,0)
  silkscreen extent -3.33,-1.87 7.88,2.96

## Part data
1 5 7 10 34 53 54 55 60 64 70 71 75 ca1 ca2: library part "CAP SMD 0805", "CAP 0805"
2 4 47 C1 C2 C3: library part "Cap ELECTROLITIC TOTAL SIZE", "Cap electrolitic radial"
3: library part "Inductor 4.7µH SMD 3x3.2mm", "Inductor 4.7µH SMD 3x3.2mm", Operating Temperature="-40°C ~ 125°C", Tolerance=±20%
6: library part LM2596S-5.0, Package=None
8 9 11 12 13 14 15 16 17 18 20 21 22 23 24 25 26 27 28 29 30 31 32 33 35 36 37 38 39 40 41 42 43 44 45 46 48 49 50 51 52 54 55 56 57 58 59 61 62 63 65 66 67 68 69 72 73 74 76: library part "RES 1206 0.25W", "RES 1206"
19: library part CURRENT-ACS712ELCTR-05B-T(SOIC8-5X4MM), "Current Sensor 5A 1 Channel Hall Effect, Open Loop Bidirectional 8-SOIC _0.154, 3.90mm Width_", Package="SOIC-8 Allegro MicroSystems LLC"
ams1 ams2 ams3: library part LM1117IMP-x.x, "x.x Volt, 800mA Low-Dropout Linear Regulator, 4-pin SOT-223", Manufacturer="National Semiconductor", PackageTopMarking=XYTT*N05B, PartNumber=LM1117IMP-3.3, PowerWise=N, Supplier Part Number 1=7614123
BC1 BC2 BC3 BC4 BC5 BC6 BC7 BC8 BC9 BC11 BC12 BC14 BC15 BC16: "45 V, 500 mA NPN general-purpose transistors"
BC10 BC13: "PNP General-purpose Transistor"
buzzer1 buzzer2 In+1 Inbutton1 Inbutton2 Inbutton3 Inbutton4 led1 led2 pinIN1: library part "Header 2", "Header, 2-Pin"
D1 D2 D4: library part "LED SMD PACKAGE", "SMD Mono-color Chip LED Waterclear", Forward Voltage="3.2 V", Part Number=150080BS75000
D3 D14: Package=None
D5 D6 D7 D8 D9 D10 D11 D12 D13: library part "1N4148 SMD", "General Semicoductor"
Din1 ss1: library part "Diode DIP Package", "Diode DIP Package"
DZ1 DZ2 DZ3: library part "ZENER GENERAL DIODE", "DIODE ZENER GENERAL"
L1: "Radial Coil Inductor", Package=None
P1: library part "Header 10", "Header, 10-Pin"
P2 P5 P7 P8: library part "Header 4", "Header, 4-Pin"
P3: library part "Header 5X2", "Header, 5-Pin, Dual row"
P4: library part "Header 8", "Header, 8-Pin"
P6: library part "Header 3", "Header, 3-Pin"
Q1: library part IRF3205PBF, "N-Channel 55V 110A _Tc_ 200W _Tc_ Through Hole TO-220AB", Package="TO-220 International Rectifier"
rele1 rele2 rele3 rele4 rele11: library part "RELAY General", "Relay_SPDT POWER NEEDLE"
rele5 rele6 rele7 rele8 rele9 rele10: library part V23105A5301A201, "Industrial Control, Relays, I/O Modules, spdt, relay, Relays and Accessories", Package=None
U1: library part LM358DRG3, "Dual, 30-V, 700-kHz operational amplifier", Package="SOIC-8 Texas Instruments"
U2: library part TC4420CPA, "Microchip MOSFET Power Driver 6A 4.5 to 18V Non-Inverting 8-Pin PDIP", Package="DIP-8 Microchip"
U3: "ARM® Cortex®-M3 STM32F1 Microcontroller IC 32-Bit 72MHz 512KB (512K x 8) FLASH 64-LQFP (10x10)", Package="LQFP-64 STMicroelectronics"
U4: "1/1 Приемопередатчик Половина CANbus 8-SO", Package="SO-8 NXP Semiconductors"
Y1: library part CRYSTAL, "Crystal"

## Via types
v1: diameter 1, hole 0.5, Top Layer to Bottom Layer, 140 vias
v2: diameter 1.5, hole 1, Top Layer to Bottom Layer, 15 vias
v3: diameter 0.8, hole 0.5, Top Layer to Bottom Layer, 12 vias
v4: diameter 1.27, hole 0.711, Top Layer to Bottom Layer, 6 vias
v5: diameter 2, hole 1, Top Layer to Bottom Layer, 5 vias
v6: diameter 1.5, hole 0.5, Top Layer to Bottom Layer, 3 vias
v7: diameter 1.4, hole 0.5, Top Layer to Bottom Layer, 2 vias
v8: diameter 0.9, hole 0.5, Top Layer to Bottom Layer, 2 vias
v9: diameter 1.2, hole 0.5, Top Layer to Bottom Layer, 1 vias

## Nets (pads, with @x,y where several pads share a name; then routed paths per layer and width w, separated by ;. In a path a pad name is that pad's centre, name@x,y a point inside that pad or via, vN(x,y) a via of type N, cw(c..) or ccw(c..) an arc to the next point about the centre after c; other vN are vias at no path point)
3.3ads: 34.1 40.1 65.2 67.2 ams2.2 ams2.4 C2.1 P1.1 P2.2 | length 53.9
  Top Layer w0.5: v4(84.074,120.777) 84.074,108.407 84.684,107.798 ; P1.1@92.989,116.129 95.098,116.129 97.13,114.097 34.1@97.13,107.903
  Top Layer w1: P2.2@80.01,106.299 82.347,106.299 C2.1@82.956,106.909 ; C2.1@82.906,106.401 84.303,107.798 84.684,107.798 ; 84.633,107.848 ams2.4@86.787,107.798 ams2.2@92.587,107.798 97.024,107.798 34.1@97.13,107.903
  Bottom Layer w1: v4(84.074,120.777) 84.074,129.901 40.1@85.674,131.502
+: rele5.8 rele6.4 | length 18.5
  Bottom Layer w1: rele5.8@125.603,209.838 128.05,207.391 131.775,207.391 133.325,205.842 133.325,202.565 136.085,199.805 rele6.4@138.049,199.805
+5v: 1.1 2.1 3.2 6.4 25.2 41.2 ams1.3 ams2.3 ams3.3 BC13.2 D5.2 D6.2 D7.2 D8.2 D9.2 D10.2 D11.2 D12.2 D13.2 D14.C rele1.5 rele2.5 rele3.5 rele4.5 rele5.16 rele6.16 rele7.16 rele8.16 rele9.16 rele10.16 rele11.5 U2.1 U2.8 | length 547.5
  Top Layer w0.5: BC13.2@112.786,152.901 113.241,152.901 v1(113.944,152.197) ; D13.2@136.371,143.789 D13.2@136.576,143.789 ; v1(143.231,130.632) 143.586,130.988 152.07,130.988 153.619,129.438 153.619,127.432 154.33,126.721 156.083,126.721
  Top Layer w0.7: 25.2@110.134,206.203 110.134,196.775 rele4.5@113.278,193.632 ; D13.2@136.576,143.789 139.675,146.888 rele11.5@139.675,149.327 ; 156.083,126.721 158.039,124.765
  Top Layer w0.9: 77.368,89.027 77.368,162.89
  Top Layer w1: v5(70.942,186.665) 61.29,177.013 61.29,168.732 66.269,163.754 76.505,163.754 77.368,162.89 ; rele1.5@71.222,193.878 73.939,196.596 82.646,196.596 rele2.5@85.363,193.878 ; 77.368,89.027 79.299,87.097 86.335,87.097 ; 77.368,100.279 87.757,100.279 89.56,102.083 v2(89.56,102.591) ; ams3.3@85.18,89.734 85.18,88.251 86.335,87.097 ; 3.2@116.916,90.373 118.085,90.373 119.763,92.051 6.4@124.842,92.051 ; U2.1@117.831,145.798 117.831,147.295 118.847,148.311 126.619,148.311 128.295,146.634 128.295,143.535 130.581,141.249 134.747,141.249 136.371,142.873 D13.2@136.371,143.789 ; v1(133.985,101.727) 133.299,101.041 111.887,101.041 108.356,97.511 2.1@108.356,95.095 106.042,95.095 102.173,91.225 ams1.3@102.173,89.962 102.173,88.203 101.067,87.097 86.335,87.097 ; rele11.5@139.675,149.327 140.157,149.809 148.412,149.809 149.606,148.615 v1(149.606,146.558) 147.803,144.755 147.803,142.621 v1(143.18,137.998) ; v1(144.526,102.616) 149.555,102.616 158.039,111.1 158.039,124.765 ; rele10.16@156.439,178.791 v4(156.439,185.623)
  Bottom Layer w0.25: v1(143.18,137.998) v1@143.231,137.947
  Bottom Layer w0.3: v1(143.231,130.632) v1@143.231,137.947
  Bottom Layer w0.5: rele6.16@130.429,192.185 130.429,190.604 D8.2@131.65,189.382 ; rele7.16@142.621,192.202 142.621,190.248 D9.2@143.664,189.205 ; rele8.16@155.067,192.075 155.067,190.324 D10.2@156.11,189.281 156.439,188.953 v4(156.439,185.623) ; rele10.16@156.439,178.791 156.591,178.638 D12.2@156.591,176.733 ; rele9.16@167.64,192.075 167.64,189.892 D11.2@168.328,189.205
  Bottom Layer w0.6: v1(133.985,101.727) 143.637,101.727 v1(144.526,102.616)
  Bottom Layer w0.8: rele2.5@85.363,194.863 87.452,196.952 95.944,196.952 rele3.5@99.26,193.636 101.839,196.215 110.695,196.215 rele4.5@113.278,193.632
  Bottom Layer w1: v5(70.942,186.665) 70.942,193.599 rele1.5@71.222,193.878 ; D5.2@82.345,188.443 82.956,188.443 85.363,190.85 rele2.5@85.363,193.878 rele2.5@85.363,194.863 ; v2(89.56,102.591) 89.56,108.991 90.678,110.109 v2(93.701,110.109) ; 2.1@108.356,95.095 109.861,95.095 1.1@110.312,94.644 114.499,94.644 116.916,92.227 v2(116.916,89.84) ; D6.2@110.132,188.163 110.998,188.163 113.278,190.443 rele4.5@113.278,193.632 116.409,193.632 rele5.16@117.983,192.058 ; v1(113.944,152.197) 113.944,152.629 114.984,153.668 U2.8@117.831,153.668 U2.1@117.831,145.798 ; D7.2@119.761,189.23 119.761,190.28 rele5.16@117.983,192.058 ; rele6.16@130.429,192.185 130.429,194.488 ; 142.469,194.488 142.621,194.335 rele7.16@142.621,192.202 ; 155.016,194.488 155.067,194.437 rele8.16@155.067,192.075 ; rele9.16@167.64,192.075 165.227,194.488 130.429,194.488 ; rele5.16@117.983,192.058 120.413,194.488 130.429,194.488
+12in: 6.1 10.2 35.2 54.1@156.921,104.755 63.2 BC10.2 C1.1 Din1.2 rele3.3 | length 322.1
  Top Layer w0.7: v1(97.511,188.062) 96.977,188.595 96.977,201.353 rele3.3@99.26,203.636
  Top Layer w1: v1(76.327,177.038) 77.394,178.105 86.157,178.105 91.364,183.312 v1(91.364,183.388) ; v5(100.178,209.956) 105.156,214.935 177.368,214.935 178.308,213.995 178.308,166.243 176.301,164.236 160.96,164.236 159.944,163.22 159.944,103.607 158.369,102.032 v5(157.353,102.032)
  Bottom Layer w0.25: 63.2@145.734,113.538 63.2@146.126,113.146 ; v5@156.921,102.464 v5(157.353,102.032)
  Bottom Layer w0.5: 35.2@75.469,175.616 75.469,176.023 BC10.2@76.484,177.038 v1(76.327,177.038) ; v1(91.364,183.388) v1@91.364,183.617 ; v5@156.921,102.464 54.1@156.921,104.755
  Bottom Layer w0.6: 63.2@146.126,113.146 146.126,101.545 10.2@148.561,99.111
  Bottom Layer w0.7: v1@91.364,183.617 92.481,184.734 96.164,184.734 97.511,186.08 v1(97.511,188.062)
  Bottom Layer w1: rele3.3@99.26,203.636 99.26,209.039 v5(100.178,209.956) ; v2(123.165,97.866) 123.52,98.222 140.157,98.222 Din1.2@142.9,95.479 142.9,95.91 144.12,97.13 C1.1@148.209,97.13 148.561,97.481 10.2@148.561,99.111 148.561,100.606 149.987,102.032 v5(157.353,102.032)
ads: 39.2 40.2 rele8.6 | length 143.5
  Top Layer w0.5: 117.119,161.696 117.119,162.027
  Top Layer w1: v1(99.949,145.364) 106.096,151.511 106.096,154.711 111.684,160.299 115.722,160.299 117.119,161.696 ; 117.119,162.027 117.119,175.311 121.031,179.222 v1(128.372,179.222) ; v1(140.614,180.213) 141.656,180.213 144.856,183.413 144.856,196.367 v1(144.018,197.206)
  Bottom Layer w0.5: 40.2@85.674,135.402 85.801,135.275 39.2@88.798,135.275 ; 94.932,145.123 95.174,145.364 ; rele8.6@162.687,204.775 163.627,204.775 166.116,202.286 168.148,202.286 169.799,200.635 169.799,197.866 168.504,196.571
  Bottom Layer w0.6: v1(144.018,197.206) 144.653,196.571 168.504,196.571
  Bottom Layer w1: 39.2@88.798,135.275 88.798,138.989 94.932,145.123 ; 95.174,145.364 v1(99.949,145.364) ; v1(128.372,179.222) 139.624,179.222 v1(140.614,180.213)
freq: 12.2 rele7.6 | length 33.1
  Top Layer w1: 12.2@149.854,174.625 149.854,178.441 146.66,181.635 146.66,201.32 rele7.6@150.241,204.902
GND: 1.2 2.2 4.2 5.1 6.3 6.5 6.6 7.2 10.1 11.1 17.2 18.2 19.5 20.2 34.2 42.1 43.1 44.1 52.1 53.2 54.2@108.567,119.079 55.2@124.007,129.972 56.2 57.1 60.1 64.1 70.1 71.2 76.2 ams1.1 ams2.1 ams3.1 BC1.2 BC2.2 BC3.2 BC4.2 BC5.2 BC6.2 BC7.2 BC8.2 BC9.2 BC11.2 BC12.2 BC14.2 BC15.2 BC16.2 C1.2 C2.2 C3.2 ca1.1 ca2.1 D2.1 D4.1 DZ1.1 DZ2.1 DZ3.1 In+1.2 led1.2 led2.2 P1.2 P2.1 P3.2 P5.4 P6.3 P7.4 P8.4 Q1.3 rele5.11 rele6.11 rele7.11 rele8.11 ss1.1 U1.2 U1.4 U2.4 U2.5 U3.12 U3.18 U3.31 U3.47 U3.63 U4.2 | length 1204.7
  Top Layer w0.25: 113.591,122.989 U3.12@119.4,122.989 122.329,122.989 122.885,123.546 122.885,125.247 121.82,126.313 U3.63@121.82,130.409 121.82,132.231 v1(121.691,132.359) ; U3.18@121.82,119.069 121.82,122.988 ; v1(126.619,125.552) 126.619,127.305 127.304,127.989 U3.47@130.74,127.989 ; v1(126.797,122.809) 127.305,122.809 128.32,121.794 ; BC16.2@143.962,115.367 144.501,115.367
  Top Layer w0.3: U3.31@128.32,119.069 128.32,121.794
  Top Layer w0.4: 108.42,117.818 113.591,122.989
  Top Layer w0.5: 77.8,209.118 78.515,208.403 ca1.1@81.153,208.403 ; 70.1@83.003,152.455 83.998,151.46 ; v1(88.443,189.027) 90.856,186.614 112.293,186.614 v1(113.919,188.239) ; D2.1@92.287,174.6 94.869,174.6 95.682,175.412 99.894,175.412 100.051,175.256 100.051,169.647 99.593,169.189 U1.4@97.479,169.189 v1(97.225,168.935) ; P1.2@92.989,118.669 96.368,118.669 99.847,115.189 99.847,106.248 98.802,105.203 34.2@97.13,105.203 ; U1.2@97.479,171.729 99.847,171.729 ; 7.2@99.844,175.463 99.844,176.679 100.152,176.987 103.734,176.987 ; 101.346,103.353 101.346,110.744 108.42,117.818 104.826,121.412 v1(104.826,123.393) ; v1(106.401,180.492) 106.401,179.299 105.842,178.74 DZ3.1@103.86,178.74 103.86,177.113 103.734,176.987 ; DZ2.1@107.365,165.202 109.296,165.202 110.007,165.913 110.007,169.037 109.237,169.808 107.925,169.808 107.925,174.498 105.435,176.987 103.734,176.987 ; BC15.2@113.929,145.406 113.929,142.331 115.926,140.335 123.876,140.335 125.451,141.91 U2.4@125.451,145.798 ; 142.215,100.711 142.215,105.867 144.501,108.153 144.501,115.367 ; BC16.2@143.962,115.367 146.761,118.166 146.761,123.749 148.057,125.044 P7.4@149.174,125.044 149.301,125.171 P8.4@155.397,125.171
  Top Layer w0.6: 83.998,151.46 U4.2@86.58,151.46 ; v3(155.423,161.214) 156.667,159.969 P5.4@156.667,148.92
  Top Layer w0.7: v1(128.422,187.3) 128.422,181.864 129.794,180.492 129.794,177.775 v1(129.286,177.267) ; 136.068,171.687 BC1.2@144.084,171.687
  Top Layer w0.8: 98.247,100.254 101.346,103.353
  Top Layer w1: v2(61.57,184.302) 61.57,185.369 64.948,188.747 88.163,188.747 v1(88.443,189.027) ; P2.1@80.01,103.759 80.035,103.784 82.982,103.784 C2.2@83.007,103.81 ; v1(86.792,168.859) 87.554,168.097 v1(87.554,162.433) ; v2(92.583,105.156) 92.63,105.203 34.2@97.13,105.203 ; v2(97.573,88.81) 94.073,88.81 4.2@91.313,91.57 90.167,91.57 89.078,92.659 89.078,97.765 91.567,100.254 98.247,100.254 ; rele5.11@117.983,204.758 117.983,206.273 119.126,207.416 130.302,207.416 ; v1(124.358,187.3) v1(128.422,187.3) ; 6.3@124.842,93.751 6.6@135.592,93.751 135.592,95.384 140.919,100.711 ; 52.1@127.076,170.547 124.677,170.547 122.911,172.314 122.911,175.006 125.171,177.267 v1(129.286,177.267) ; rele6.11@130.429,204.885 130.429,207.289 130.302,207.416 ; 44.1@135.173,174.498 136.068,173.603 136.068,171.687 ; v1(137.074,187.188) 139.603,184.658 v1(142.24,184.658) ; 141.097,100.711 142.215,100.711 150.571,100.711 151.709,99.573 C1.2@151.709,97.13 ; rele7.11@142.621,204.902 142.621,207.239 142.799,207.416 ; v1(148.471,185.478) 150.622,187.63 v1(161.823,187.63) 174.168,187.63 v1(174.371,187.427) ; rele8.11@155.067,204.775 155.067,207.188 154.838,207.416 142.799,207.416 ; led2.2@155.296,128.27 led2.2@155.296,128.473 155.296,129.946 P6.3@157.201,131.851 ; 130.302,207.416 142.799,207.416
  Bottom Layer w0.25: v1@113.767,133.071 v1(113.868,132.969) ; v1(128.422,187.3) 136.499,187.3 ; v1(137.074,187.188) BC5.2@137.074,187.875 ; 159.715,148.92 159.842,149.047
  Bottom Layer w0.4: v3(155.423,161.214) 155.844,161.635 BC9.2@155.844,167.428
  Bottom Layer w0.5: BC14.2@73.67,179.866 73.67,183.576 76.022,185.928 81.763,185.928 82.474,185.217 ; ca2.1@73.736,209.521 74.418,208.839 v1(77.114,208.839) ; v2@82.728,152.375 76.2@87.153,152.375 ; 92.431,100.025 115.468,100.025 117.018,101.575 P3.2@117.018,104.724 117.039,104.746 53.2@118.974,104.746 ; 18.2@96.942,165.801 18.2@97.225,165.518 ; v1(113.868,132.969) 114.021,133.121 120.929,133.121 v1(121.691,132.359) ; v1(119.786,140.437) 119.786,134.264 v1(121.691,132.359) ; 55.2@124.007,129.972 125.679,129.972 125.933,130.226 ; 42.1@124.226,149.657 125.451,149.657 ; v1(126.797,122.809) 126.797,129.718 124.155,132.359 v1(121.691,132.359) ; v1(136.068,171.069) 136.576,171.577 17.2@141.941,171.577 ; v1(148.471,185.478) 149.291,186.299 BC6.2@149.291,188.129
  Bottom Layer w0.6: 61.153,185.496 BC2.2@61.153,190.161
  Bottom Layer w0.7: 126.415,145.798 BC11.2@128.388,143.825
  Bottom Layer w0.8: 61.153,170.292 61.153,185.496
  Bottom Layer w1: 61.153,170.292 63.779,167.665 75.59,167.665 77.292,165.964 77.292,152.629 ; P2.1@80.01,103.759 81.813,101.956 81.813,100.025 ; v2(80.315,89.865) 80.315,98.527 81.813,100.025 ; v2@80.449,89.865 80.449,87.554 81.432,87.554 ; v1(81.153,208.559) 83.21,208.559 84.684,210.033 84.684,212.395 87.274,214.986 113.843,214.986 113.843,208.898 rele5.11@117.983,204.758 ; v2@82.601,152.375 81.89,152.375 81.636,152.629 77.292,152.629 ; Q1.3@82.779,180.975 82.779,183.179 43.1@82.316,183.642 82.474,183.8 82.474,185.217 82.474,185.547 85.573,185.547 88.443,188.417 v1(88.443,189.027) ; 71.2@83.261,151.108 83.261,151.841 82.728,152.375 v2(82.601,152.502) 82.601,157.48 v1(87.554,162.433) ; v1(86.792,168.859) 86.792,175.844 93.644,182.696 11.1@96.469,182.696 104.832,182.696 106.401,181.127 v1(106.401,180.492) ; C3.2@87.63,91.872 87.932,91.57 4.2@91.313,91.57 92.869,91.57 5.1@93.396,92.097 ; v2(92.583,105.156) 92.583,100.178 92.431,100.025 81.813,100.025 ; v1(94.488,166.092) 96.652,166.092 18.2@96.942,165.801 ; v1(97.225,168.935) 97.225,165.518 18.2@97.288,165.456 ; v2(97.573,88.81) 97.573,87.554 ; 64.1@104.924,123.622 60.1@104.924,128.549 ; 1.2@110.312,91.944 109.963,91.595 2.2@108.356,91.595 ; v1(113.919,188.239) 115.9,186.258 123.315,186.258 v1(124.358,187.3) ; 114.097,214.986 163.424,214.986 ; U2.5@125.451,153.668 125.451,149.657 U2.4@125.451,145.798 126.415,145.798 ; v1(128.422,187.3) 128.535,187.188 v1(137.074,187.188) ; v1(129.286,177.267) 133.579,177.267 136.068,174.777 v1(136.068,171.069) 141.433,171.069 17.2@141.941,171.577 ; v2(135.56,93.421) 133.477,91.338 ss1.1@130.429,91.338 129.413,90.322 v2(122.326,90.322) 122.326,89.814 119.786,87.274 112.573,87.274 108.356,91.491 2.2@108.356,91.595 ; v1(142.24,184.658) 147.65,184.658 v1(148.471,185.478) ; P7.4@149.174,125.044 led1.2@149.174,128.346 ; 10.1@151.261,99.111 151.486,98.886 151.486,97.353 C1.2@151.709,97.13 153.695,97.13 In+1.2@156.388,94.945 ; led2.2@155.296,128.473 155.296,125.273 P8.4@155.397,125.171 ; In+1.2@156.337,94.488 157.963,94.488 159.842,96.368 159.842,112.928 ; 57.1@156.87,112.872 159.786,112.872 159.842,112.928 ; P5.4@157.302,148.92 159.715,148.92 ; 163.449,214.986 177.241,214.986 178.359,213.868 178.359,166.294 176.301,164.236 160.833,164.236 159.842,163.246 159.842,149.047 159.842,112.928 ; 77.292,152.629 77.292,88.849 78.588,87.554 81.432,87.554 ; 81.432,87.554 97.573,87.554 ; 97.573,87.554 104.315,87.554 2.2@108.356,91.595
in1: 13.2 22.2 rele5.6 | length 45.5
  Top Layer w1: 13.2@96.444,182.696 115.793,182.696 121.615,188.519 121.615,200.77 rele5.6@125.603,204.758
Net3_1: 3.1 6.2 ss1.2 | length 14.2
  Top Layer w1: 3.1@116.688,96.444 117.678,95.453 v2(122.352,95.453)
  Bottom Layer w1: v2(122.352,95.453) 122.377,95.428 130.26,95.428 ss1.2@130.429,95.258
Net8_1: 8.1 14.1 U1.1 | length 7
  Top Layer w0.5: v1(93.675,171.856) 94.513,171.856 95.656,172.999 U1.1@97.479,172.999
  Bottom Layer w1: 8.1@93.085,171.882 14.1@93.085,174.6
Net8_2: 8.2 D1.1 | length 1.2
  Top Layer w0.5: v1(88.951,171.78) D1.1@90.187,171.78
Net12_1: 12.1 17.1 BC1.1 | length 3.4
  Top Layer w0.5: 12.1@145.954,174.625 145.984,174.595 BC1.1@145.984,171.687
  Bottom Layer w0.5: 17.1@145.841,171.577 v1(146.279,171.577)
Net14_2: 14.2 D2.2 | length 1.1
  Top Layer w0.5: v1(89.103,174.6) D2.2@90.187,174.6
Net15_1: 15.1 21.1 U1.7 | length 3.4
  Top Layer w0.5: U1.7@102.419,171.729 102.476,171.673 21.1@105.689,171.673
  Bottom Layer w0.5: 15.1@105.715,171.673 v1(105.715,171.78)
Net16_1: 16.1 18.1 U1.5 | length 4.2
  Bottom Layer w1: v1(101.188,165.258) 102.565,166.636 v1(102.565,168.885)
Net19_1: 19.1 19.2 pinIN1.1 | length 5.2
  Top Layer w0.5: 19.2@71.036,211.658 71.036,212.42
  Top Layer w1: pinIN1.1@67.208,212.42 71.222,212.42 71.222,212.225 71.036,212.039
Net19_3: 19.3 19.4 rele1.1 | length 21.7
  Top Layer w1: rele1.1@66.272,191.428 66.272,206.886 68.809,209.423 70.782,209.423 19.3@70.782,210.134
Net19_6: 19.6 ca1.2 | length 5.1
  Top Layer w0.5: 19.6@76.436,210.388 78.715,210.388 79.43,211.103 ca1.2@81.204,211.103
Net20_1: 20.1 Inbutton2.2 rele9.11 | length 23.9
  Top Layer w0.7: rele9.11@167.64,204.775 165.202,207.213 165.202,211.607 166.472,212.877 Inbutton2.2@169.926,212.877
  Bottom Layer w0.5: rele9.11@167.386,204.775 167.386,204.521 173.361,198.546 20.1@173.361,196.418
Net21_2: 21.2 D4.2 | length 2.3
  Top Layer w0.5: 21.2@105.689,167.773 105.755,167.708 D4.2@107.925,167.708
Net22_1: 22.1 D3.C DZ3.2 | length 0.2
  Bottom Layer w1: v5(99.72,178.714) D3.C@99.942,178.714
Net24_1: 24.1 Inbutton2.1 rele9.6 | length 23.7
  Top Layer w1: rele9.6@174.904,204.775 rele9.6@175.006,204.775 rele9.6@175.26,204.775
  Bottom Layer w0.25: 172.237,210.541 172.466,210.769
  Bottom Layer w0.4: 162.433,212.801 167.64,212.801 169.901,210.541 172.237,210.541
  Bottom Layer w0.5: v6(159.557,212.801) 162.433,212.801 ; rele9.6@175.057,204.826 175.108,204.775 rele9.6@175.26,204.775
  Bottom Layer w0.7: Inbutton2.1@172.466,212.877 172.466,210.769 172.466,207.315 rele9.6@175.006,204.775
Net26_1: 26.1 BC2.1 | length 2.3
  Bottom Layer w0.5: 26.1@63.023,187.376 BC2.1@63.023,189.704
Net27_1: 27.1 BC3.1 | length 1.8
  Bottom Layer w0.5: BC3.1@90.145,189.286 90.145,188.067 27.1@90.582,187.63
